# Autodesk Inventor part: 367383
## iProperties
Created: 2006-07
Part Number: 367383
Material: A2
Description: Zylinderschraube
Vendor: Autodesk Inc.
Document SubType Name: Modeling
Standard: DIN 912
Designer: I.Baliuc
Standards Organization: DIN
Language: de-DE
Size Designation: M6 x 25
Categories: <MemberInstance Version="R10.0.0"><Categories><Category DisplayName="Schrauben" InternalName="e4da775c-781d-43d5-af7c-5136215cf5a6" Mnemonic="FSTN"><Category Di
Density: 8.08 g/cm^3
Abmessung: M6 x 25
Author: T.Messerschmitt
Comments: DIN 912 - M6 x 25
Revision Number: 367383
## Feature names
1. Körper [Revolution]
2. Loch [Extrusion]
3. Rundung1 [Fillet]
4. Fase1 [Chamfer]
